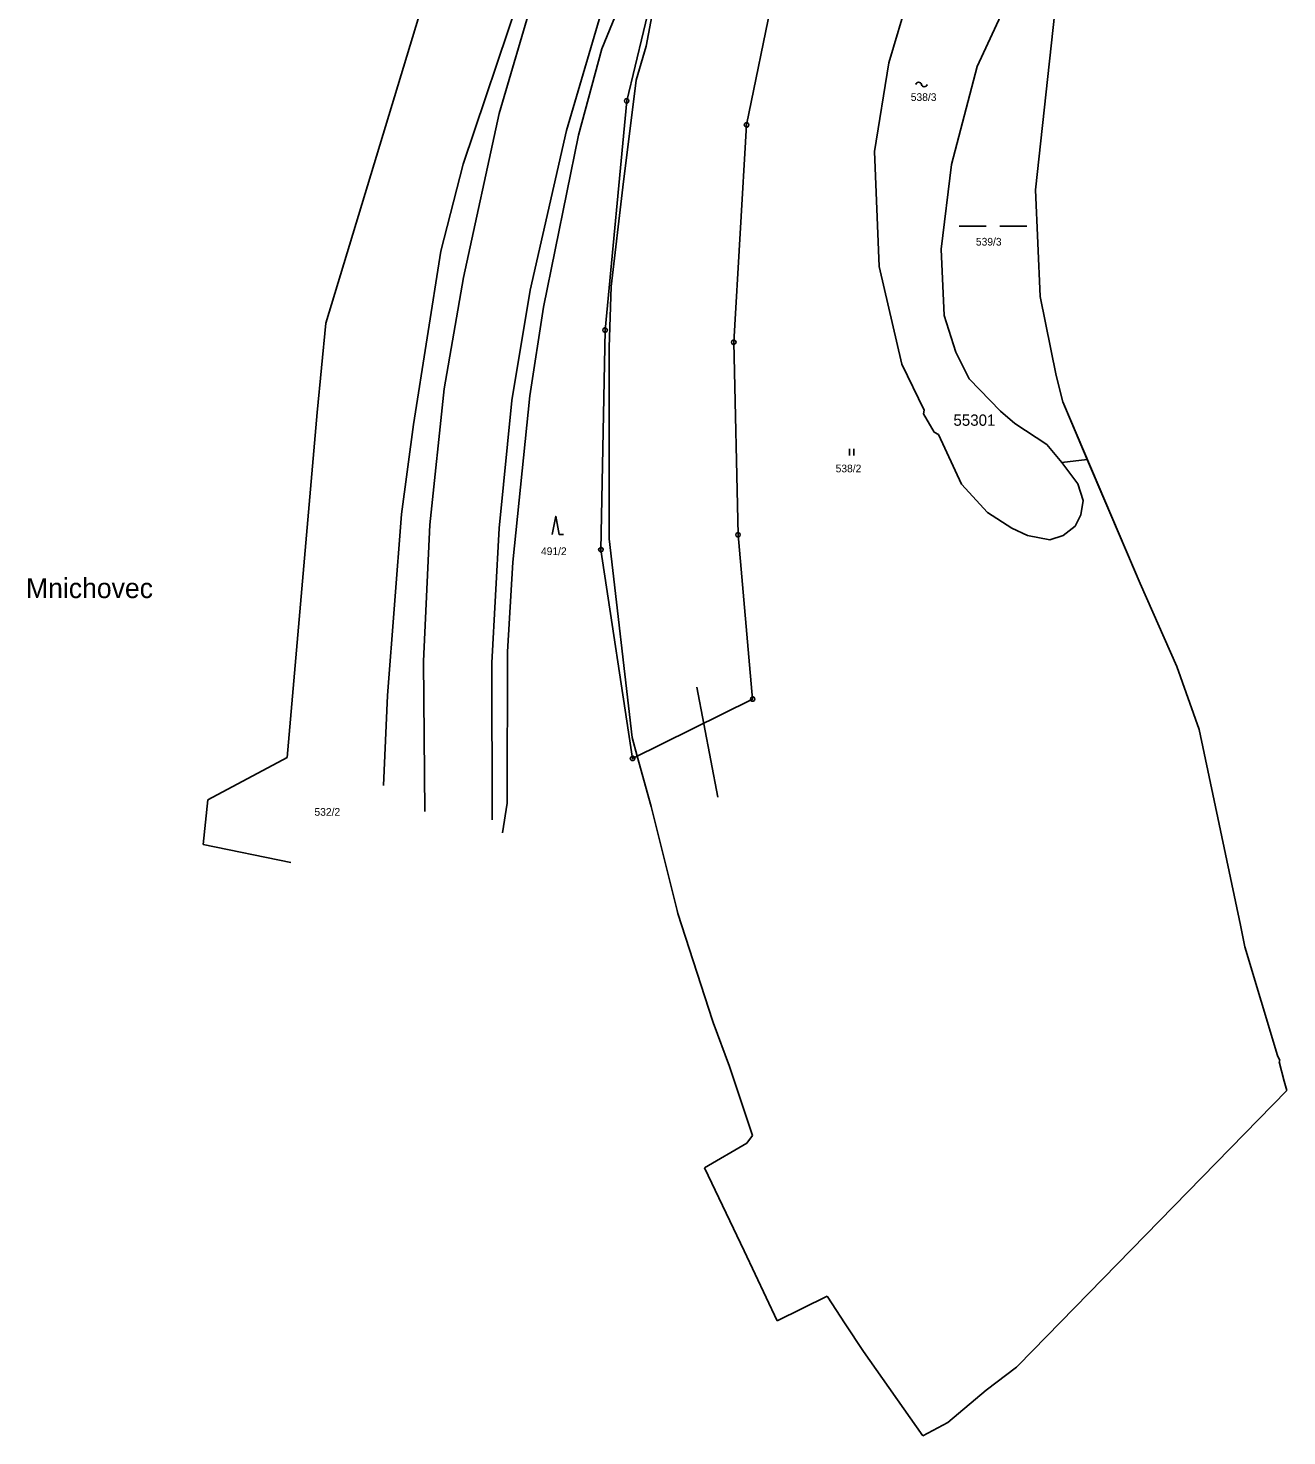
# Model space of a CAD drawing. Extents: x -759699 to -757730, y -1172308 to -1170857.
# Drawn here: x -759603.2 to -759324.5, y -1172307.8 to -1171996 of the extents above; entities that cross this region are included whole.
import ezdxf

# ---------------------------------------------------------------- set-up
doc = ezdxf.new("R2010")
doc.units = 0
for name, color, linetype in [('Vrstva 1', 7, 'Continuous'), ('Vrstva 11', 7, 'Continuous'), ('Vrstva 12', 7, 'Continuous'), ('Vrstva 2', 7, 'Continuous'), ('Vrstva 3', 7, 'Continuous'), ('Vrstva 4', 7, 'Continuous'), ('Vrstva 5', 7, 'Continuous'), ('Vrstva 6', 7, 'Continuous'), ('Vrstva 7', 7, 'Continuous'), ('Vrstva 8', 7, 'Continuous')]:
    doc.layers.add(name, color=color, linetype=linetype)

msp = doc.modelspace()

# ---------------------------------------------------------------- linework, layer by layer
at = {"layer": 'Vrstva 1'}
for p, q in [((-759452.74, -1171943.04), (-759476.19, -1172000.56)), ((-759430.13, -1171948.96), (-759444.14, -1172017.45)), ((-759470.68, -1172012.13), (-759458.91, -1171963.39)), ((-759506.88, -1172026.13), (-759487.37, -1171967.99)), ((-759373.78, -1171972.82), (-759380.16, -1172031.84)), ((-759393.04, -1172004.47), (-759379.74, -1171975.75)), ((-759406.63, -1171983.37), (-759412.61, -1172003.66)), ((-759537.32, -1172061.35), (-759514.41, -1171985.91)), ((-759476.19, -1172000.56), (-759481.37, -1172019.73)), ((-759412.61, -1172003.66), (-759415.84, -1172023.33)), ((-759398.74, -1172026.24), (-759393.04, -1172004.47)), ((-759475.45, -1172062.9), (-759470.68, -1172012.13)), ((-759446.97, -1172065.59), (-759444.14, -1172017.45)), ((-759481.37, -1172019.73), (-759489.08, -1172057.83)), ((-759415.84, -1172023.33), (-759414.74, -1172048.8)), ((-759511.86, -1172045.41), (-759506.88, -1172026.13)), ((-759401.01, -1172044.97), (-759398.74, -1172026.24)), ((-759380.16, -1172031.84), (-759379.09, -1172055.43)), ((-759517.92, -1172083.82), (-759511.86, -1172045.41)), ((-759400.38, -1172059.65), (-759401.01, -1172044.97)), ((-759414.74, -1172048.8), (-759409.74, -1172070.42)), ((-759379.09, -1172055.43), (-759375.57, -1172072.91)), ((-759489.08, -1172057.83), (-759492.14, -1172077.48)), ((-759397.83, -1172067.81), (-759400.38, -1172059.65)), ((-759539.23, -1172081.14), (-759537.32, -1172061.35)), ((-759476.38, -1172111.53), (-759475.45, -1172062.9)), ((-759446.97, -1172065.59), (-759446.02, -1172108.24)), ((-759394.81, -1172073.7), (-759397.83, -1172067.81)), ((-759409.74, -1172070.42), (-759404.82, -1172080.65)), ((-759387.89, -1172080.83), (-759394.81, -1172073.7)), ((-759375.57, -1172072.91), (-759374.13, -1172078.75)), ((-759492.14, -1172077.48), (-759495.9, -1172114.26)), ((-759539.23, -1172081.14), (-759545.89, -1172157.54)), ((-759404.82, -1172080.65), (-759404.93, -1172081.47)), ((-759404.93, -1172081.47), (-759402.59, -1172085.51)), ((-759384.71, -1172083.56), (-759387.89, -1172080.83)), ((-759374.13, -1172078.75), (-759368.69, -1172091.54)), ((-759520.51, -1172103.63), (-759517.92, -1172083.82)), ((-759377.67, -1172088.25), (-759384.71, -1172083.56)), ((-759402.59, -1172085.51), (-759401.66, -1172085.99)), ((-759401.66, -1172085.99), (-759396.57, -1172097.04)), ((-759374.3, -1172092.19), (-759377.67, -1172088.25)), ((-759374.3, -1172092.19), (-759368.69, -1172091.54)), ((-759370.8, -1172096.95), (-759374.3, -1172092.19)), ((-759368.69, -1172091.54), (-759357, -1172119.01)), ((-759396.57, -1172097.04), (-759390.82, -1172103.28)), ((-759369.61, -1172100.61), (-759370.8, -1172096.95)), ((-759390.82, -1172103.28), (-759385.36, -1172106.73)), ((-759370.12, -1172103.84), (-759369.61, -1172100.61)), ((-759523.62, -1172143.81), (-759520.51, -1172103.63)), ((-759374.01, -1172108.41), (-759371.39, -1172106.31)), ((-759371.39, -1172106.31), (-759370.12, -1172103.84)), ((-759446.02, -1172108.24), (-759442.79, -1172144.64)), ((-759385.36, -1172106.73), (-759381.89, -1172108.38)), ((-759381.89, -1172108.38), (-759376.98, -1172109.36)), ((-759376.98, -1172109.36), (-759374.01, -1172108.41)), ((-759469.38, -1172157.78), (-759476.38, -1172111.53)), ((-759495.9, -1172114.26), (-759497.09, -1172134.12)), ((-759357, -1172119.01), (-759348.86, -1172137.44)), ((-759497.09, -1172134.12), (-759497.17, -1172167.68)), ((-759348.86, -1172137.44), (-759343.91, -1172151.37)), ((-759523.62, -1172143.81), (-759524.54, -1172163.74)), ((-759442.79, -1172144.64), (-759469.38, -1172157.78)), ((-759442.79, -1172144.64), (-759442.79, -1172144.64)), ((-759343.91, -1172151.37), (-759343.91, -1172151.37)), ((-759545.89, -1172157.54), (-759563.44, -1172166.97)), ((-759469.38, -1172157.78), (-759469.38, -1172157.78)), ((-759524.54, -1172163.74), (-759524.54, -1172163.74)), ((-759563.44, -1172166.97), (-759564.46, -1172176.8)), ((-759498.15, -1172174.24), (-759497.17, -1172167.68)), ((-759497.17, -1172167.68), (-759497.17, -1172167.68)), ((-759498.15, -1172174.24), (-759498.15, -1172174.24)), ((-759498.15, -1172174.24), (-759498.15, -1172174.24)), ((-759564.46, -1172176.8), (-759545.02, -1172180.85)), ((-759545.02, -1172180.85), (-759545.02, -1172180.85))]:
    msp.add_line(p, q, dxfattribs=at)
at = {"layer": 'Vrstva 11'}
for p, q in [((-759373.78, -1171972.82), (-759380.16, -1172031.84)), ((-759463.6, -1171985.04), (-759466.34, -1172000)), ((-759466.34, -1172000), (-759468.56, -1172007.5)), ((-759468.56, -1172007.5), (-759471.54, -1172031.21)), ((-759471.54, -1172031.21), (-759474.1, -1172053.22)), ((-759380.16, -1172031.84), (-759379.09, -1172055.43)), ((-759474.1, -1172053.22), (-759474.53, -1172066.77)), ((-759379.09, -1172055.43), (-759375.57, -1172072.91)), ((-759474.53, -1172066.77), (-759474.55, -1172109.11)), ((-759375.57, -1172072.91), (-759374.13, -1172078.75)), ((-759374.13, -1172078.75), (-759357, -1172119.01)), ((-759474.55, -1172109.11), (-759469.49, -1172153.16)), ((-759357, -1172119.01), (-759348.86, -1172137.44)), ((-759348.86, -1172137.44), (-759343.91, -1172151.37)), ((-759469.49, -1172153.16), (-759468.35, -1172157.27)), ((-759343.91, -1172151.37), (-759334.79, -1172194.71)), ((-759468.35, -1172157.27), (-759465.25, -1172168.41)), ((-759465.25, -1172168.41), (-759459.5, -1172191.45)), ((-759459.5, -1172191.45), (-759459.33, -1172192.13)), ((-759459.33, -1172192.13), (-759451.71, -1172215.86)), ((-759334.79, -1172194.71), (-759333.78, -1172199.51)), ((-759333.78, -1172199.51), (-759326.59, -1172223.56)), ((-759451.71, -1172215.86), (-759451.56, -1172216.26)), ((-759451.56, -1172216.26), (-759447.9, -1172226.02)), ((-759326.59, -1172223.56), (-759326.05, -1172224.71)), ((-759326.2, -1172224.99), (-759326.05, -1172224.71)), ((-759325.06, -1172229.25), (-759326.2, -1172224.99)), ((-759447.9, -1172226.02), (-759442.97, -1172240.82)), ((-759324.5, -1172231.35), (-759325.06, -1172229.25)), ((-759383.97, -1172292.26), (-759324.5, -1172231.35)), ((-759444.09, -1172242.97), (-759453.42, -1172248.46)), ((-759442.82, -1172241.28), (-759444.09, -1172242.97)), ((-759442.97, -1172240.82), (-759442.82, -1172241.28)), ((-759453.42, -1172248.46), (-759444.67, -1172266.88)), ((-759444.67, -1172266.88), (-759437.33, -1172282.36)), ((-759437.33, -1172282.36), (-759426.3, -1172276.88)), ((-759426.3, -1172276.88), (-759422.27, -1172283.03)), ((-759422.27, -1172283.03), (-759418.25, -1172289.17)), ((-759418.25, -1172289.17), (-759405.11, -1172307.83)), ((-759391.11, -1172297.69), (-759384.33, -1172292.63)), ((-759384.33, -1172292.63), (-759383.97, -1172292.26)), ((-759399.6, -1172304.87), (-759391.11, -1172297.69)), ((-759405.11, -1172307.83), (-759399.6, -1172304.87))]:
    msp.add_line(p, q, dxfattribs=at)
at = {"layer": 'Vrstva 12'}
for p, q in [((-759393.04, -1172004.47), (-759379.74, -1171975.75)), ((-759406.63, -1171983.37), (-759412.61, -1172003.66)), ((-759412.61, -1172003.66), (-759415.84, -1172023.33)), ((-759398.74, -1172026.24), (-759393.04, -1172004.47)), ((-759415.84, -1172023.33), (-759414.74, -1172048.8)), ((-759401.01, -1172044.97), (-759398.74, -1172026.24)), ((-759400.38, -1172059.65), (-759401.01, -1172044.97)), ((-759414.74, -1172048.8), (-759409.74, -1172070.42)), ((-759397.83, -1172067.81), (-759400.38, -1172059.65)), ((-759394.81, -1172073.7), (-759397.83, -1172067.81)), ((-759409.74, -1172070.42), (-759404.82, -1172080.65)), ((-759387.89, -1172080.83), (-759394.81, -1172073.7)), ((-759404.82, -1172080.65), (-759404.93, -1172081.47)), ((-759404.93, -1172081.47), (-759402.59, -1172085.51)), ((-759384.71, -1172083.56), (-759387.89, -1172080.83)), ((-759377.67, -1172088.25), (-759384.71, -1172083.56)), ((-759402.59, -1172085.51), (-759401.66, -1172085.99)), ((-759401.66, -1172085.99), (-759396.57, -1172097.04)), ((-759374.3, -1172092.19), (-759377.67, -1172088.25)), ((-759370.8, -1172096.95), (-759374.3, -1172092.19)), ((-759396.57, -1172097.04), (-759390.82, -1172103.28)), ((-759369.61, -1172100.61), (-759370.8, -1172096.95)), ((-759390.82, -1172103.28), (-759385.36, -1172106.73)), ((-759370.12, -1172103.84), (-759369.61, -1172100.61)), ((-759374.01, -1172108.41), (-759371.39, -1172106.31)), ((-759371.39, -1172106.31), (-759370.12, -1172103.84)), ((-759385.36, -1172106.73), (-759381.89, -1172108.38)), ((-759381.89, -1172108.38), (-759376.98, -1172109.36)), ((-759376.98, -1172109.36), (-759374.01, -1172108.41))]:
    msp.add_line(p, q, dxfattribs=at)
at = {"layer": 'Vrstva 3'}
for p, q in [((-759397.05, -1172039.89), (-759391.05, -1172039.89)), ((-759388.05, -1172039.89), (-759382.05, -1172039.89)), ((-759421.35, -1172089.2), (-759421.35, -1172090.7)), ((-759420.35, -1172090.7), (-759420.35, -1172089.2))]:
    msp.add_line(p, q, dxfattribs=at)
msp.add_lwpolyline([(-759487.15, -1172108.14), (-759486.4, -1172104.14), (-759485.65, -1172108.14), (-759484.65, -1172108.14)], dxfattribs=at)
at = {"layer": 'Vrstva 4'}
for p, q in [((-759498.9, -1172014.92), (-759489.42, -1171982.71)), ((-759474.89, -1171987.52), (-759484.03, -1172018.64)), ((-759506.82, -1172051.24), (-759498.9, -1172014.92)), ((-759484.03, -1172018.64), (-759492.03, -1172054.07)), ((-759511.09, -1172075.88), (-759506.82, -1172051.24)), ((-759492.03, -1172054.07), (-759496.09, -1172078.51)), ((-759514.26, -1172106.01), (-759511.09, -1172075.88)), ((-759496.09, -1172078.51), (-759498.93, -1172106.77)), ((-759515.66, -1172136.25), (-759514.26, -1172106.01)), ((-759498.93, -1172106.77), (-759500.53, -1172136.57)), ((-759515.66, -1172136.25), (-759515.35, -1172169.56)), ((-759500.46, -1172171.35), (-759500.53, -1172136.57)), ((-759515.35, -1172169.56), (-759515.35, -1172169.56)), ((-759500.46, -1172171.35), (-759500.46, -1172171.35))]:
    msp.add_line(p, q, dxfattribs=at)
at = {"layer": 'Vrstva 5'}
msp.add_lwpolyline([(-759406.66, -1172008.47), (-759406.58, -1172008.27), (-759406.44, -1172008.11), (-759406.25, -1172008.01), (-759406.04, -1172007.97), (-759405.82, -1172008.01), (-759405.64, -1172008.11), (-759405.49, -1172008.27), (-759405.41, -1172008.47), (-759405.33, -1172008.67), (-759405.19, -1172008.83), (-759405, -1172008.93), (-759404.79, -1172008.97), (-759404.57, -1172008.93), (-759404.39, -1172008.83), (-759404.24, -1172008.67), (-759404.16, -1172008.47)], dxfattribs=at)
at = {"layer": 'Vrstva 6'}
for p in [(-759455.17, -1172141.96), (-759450.5, -1172166.38)]:
    msp.add_line(p, (-759450.5, -1172166.38), dxfattribs=at)
at = {"layer": 'Vrstva 8'}
for p, q in [((-759470.8, -1172012.13), (-759470.56, -1172012.13)), ((-759444.26, -1172017.45), (-759444.02, -1172017.45)), ((-759475.57, -1172062.9), (-759475.33, -1172062.9)), ((-759447.09, -1172065.59), (-759446.85, -1172065.59)), ((-759446.14, -1172108.24), (-759445.9, -1172108.24)), ((-759476.5, -1172111.53), (-759476.26, -1172111.53)), ((-759442.91, -1172144.64), (-759442.67, -1172144.64)), ((-759469.5, -1172157.78), (-759469.26, -1172157.78))]:
    msp.add_line(p, q, dxfattribs=at)
for points in [[(-759470.53, -1172011.65), (-759470.28, -1172011.83), (-759470.18, -1172012.12), (-759470.28, -1172012.41), (-759470.53, -1172012.59), (-759470.84, -1172012.59), (-759471.09, -1172012.41), (-759471.19, -1172012.12), (-759471.09, -1172011.83), (-759470.84, -1172011.65)], [(-759443.99, -1172016.97), (-759443.74, -1172017.15), (-759443.64, -1172017.44), (-759443.74, -1172017.73), (-759443.99, -1172017.91), (-759444.3, -1172017.91), (-759444.55, -1172017.73), (-759444.65, -1172017.44), (-759444.55, -1172017.15), (-759444.3, -1172016.97)], [(-759475.3, -1172062.42), (-759475.05, -1172062.6), (-759474.95, -1172062.89), (-759475.05, -1172063.18), (-759475.3, -1172063.36), (-759475.61, -1172063.36), (-759475.86, -1172063.18), (-759475.96, -1172062.89), (-759475.86, -1172062.6), (-759475.61, -1172062.42)], [(-759446.82, -1172065.11), (-759446.57, -1172065.29), (-759446.47, -1172065.58), (-759446.57, -1172065.87), (-759446.82, -1172066.05), (-759447.13, -1172066.05), (-759447.38, -1172065.87), (-759447.48, -1172065.58), (-759447.38, -1172065.29), (-759447.13, -1172065.11)], [(-759445.87, -1172107.76), (-759445.62, -1172107.94), (-759445.52, -1172108.23), (-759445.62, -1172108.52), (-759445.87, -1172108.7), (-759446.18, -1172108.7), (-759446.43, -1172108.52), (-759446.53, -1172108.23), (-759446.43, -1172107.94), (-759446.18, -1172107.76)], [(-759476.23, -1172111.05), (-759475.98, -1172111.23), (-759475.88, -1172111.52), (-759475.98, -1172111.81), (-759476.23, -1172111.99), (-759476.54, -1172111.99), (-759476.79, -1172111.81), (-759476.89, -1172111.52), (-759476.79, -1172111.23), (-759476.54, -1172111.05)], [(-759442.64, -1172144.16), (-759442.39, -1172144.34), (-759442.29, -1172144.63), (-759442.39, -1172144.92), (-759442.64, -1172145.1), (-759442.95, -1172145.1), (-759443.2, -1172144.92), (-759443.3, -1172144.63), (-759443.2, -1172144.34), (-759442.95, -1172144.16)], [(-759469.23, -1172157.3), (-759468.98, -1172157.48), (-759468.88, -1172157.77), (-759468.98, -1172158.06), (-759469.23, -1172158.24), (-759469.54, -1172158.24), (-759469.79, -1172158.06), (-759469.89, -1172157.77), (-759469.79, -1172157.48), (-759469.54, -1172157.3)]]:
    msp.add_lwpolyline(points, close=True, dxfattribs=at)

# ---------------------------------------------------------------- texts
at = {"layer": 'Vrstva 11'}
msp.add_text('55301', height=2.5, dxfattribs=at).set_placement((-759398.327, -1172084.08))
at = {"layer": 'Vrstva 2'}
for s, p in [('538/3', (-759407.773, -1172012.12)), ('539/3', (-759393.354, -1172044.16)), ('538/2', (-759424.407, -1172094.39)), ('491/2', (-759489.659, -1172112.72)), ('532/2', (-759539.814, -1172170.47))]:
    msp.add_text(s, height=1.7, dxfattribs=at).set_placement(p)
at = {"layer": 'Vrstva 7'}
msp.add_text('Mnichovec', height=4.4, dxfattribs=at).set_placement((-759603.696, -1172122.25))

doc.saveas('drawing.dxf')
